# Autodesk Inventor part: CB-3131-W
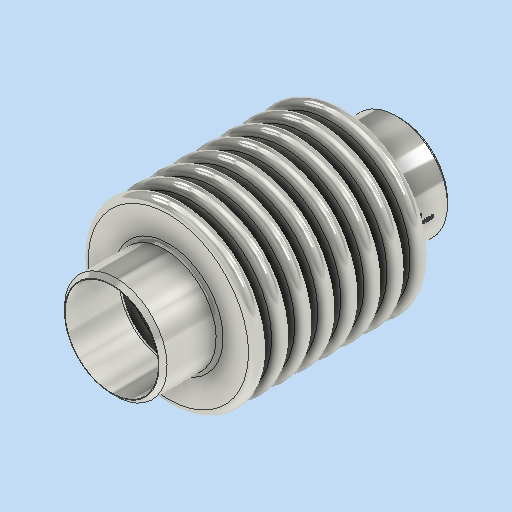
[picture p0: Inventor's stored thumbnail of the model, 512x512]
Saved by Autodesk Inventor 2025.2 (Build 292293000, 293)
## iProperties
Company: DN.RU
Created: 2026-04
Part Number: CB-3131-W
Material: Типовые
Document SubType Name: Modeling
Designer: DN.RU
Density: 6.52243 g/cm^3
Appearance: По умолчанию
Description: D140-02123
Mass: 2100 g
Surface Area: 4937.37 cm^2
Volume: 321.966 cm^3
Author: DN.RU
Title: Компенсатор сильфонный осевой DN.ru Ду80 Ру16
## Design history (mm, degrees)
sketch "Эскиз1"
  geometry: L1 (0, 0)-(0, -125); L2 (44.45, -125)-(44.45, 0); L3 (44.45, 0)-(0, 0); L4 (44.45, 0)-(44.45, -10); L5 (19.45, -10)-(69.45, -10); L6 (19.45, -16)-(69.45, -16); L7 (69.45, -4)-(19.45, -4); L8 (69.45, -15)-(19.45, -15); L9 (19.45, -5)-(69.45, -5); L10 (69.45, -24)-(19.45, -24); L11 (19.45, -25)-(69.45, -25); L12 (19.45, -30)-(69.45, -30); L13 (19.45, -36)-(69.45, -36); L14 (69.45, -35)-(19.45, -35); L15 (69.45, -44)-(19.45, -44); L16 (19.45, -45)-(69.45, -45); L17 (19.45, -50)-(69.45, -50); L18 (19.45, -56)-(69.45, -56); L19 (69.45, -55)-(19.45, -55); L20 (69.45, -64)-(19.45, -64); L21 (19.45, -65)-(69.45, -65); L22 (19.45, -70)-(69.45, -70); L23 (19.45, -76)-(69.45, -76); L24 (69.45, -75)-(19.45, -75); L25 (0, -125)-(44.45, -125); L26 (44.45, -125)-(40.45, -125); L27 (44.45, -64)-(43.45, -64); L28 (40.45, -125)-(40.45, -75); L29 (44.45, -65)-(43.45, -65); L30 (43.45, -65)-(43.45, -55); L31 (44.45, -45)-(43.45, -45); L32 (43.45, -45)-(43.45, -35); L33 (44.45, -25)-(43.45, -25); L34 (43.45, -25)-(43.45, -15); L35 (44.45, -5)-(43.45, -5); L36 (43.45, -5)-(43.45, 0); A1 r 6 centre (19.45, -10) between (19.45, -4) and (19.45, -16); A2 r 6 centre (69.45, -10) between (69.45, -16) and (69.45, -4); A3 r 5 centre (19.45, -10) between (19.45, -5) and (19.45, -15); A4 r 5 centre (69.45, -10) between (69.45, -15) and (69.45, -5); A5 r 5 centre (19.45, -30) between (19.45, -25) and (19.45, -35); A6 r 6 centre (19.45, -30) between (19.45, -24) and (19.45, -36); A7 r 5 centre (69.45, -30) between (69.45, -35) and (69.45, -25); A8 r 6 centre (69.45, -30) between (69.45, -36) and (69.45, -24); A9 r 5 centre (19.45, -50) between (19.45, -45) and (19.45, -55); A10 r 6 centre (19.45, -50) between (19.45, -44) and (19.45, -56); A11 r 5 centre (69.45, -50) between (69.45, -55) and (69.45, -45); A12 r 6 centre (69.45, -50) between (69.45, -56) and (69.45, -44); A13 r 5 centre (19.45, -70) between (19.45, -65) and (19.45, -75); A14 r 6 centre (19.45, -70) between (19.45, -64) and (19.45, -76); A15 r 5 centre (69.45, -70) between (69.45, -75) and (69.45, -65); A16 r 6 centre (69.45, -70) between (69.45, -76) and (69.45, -64); 18 further points
  constraints: 80 end point, 32 point on circle, 16 centre point, 15 point on line, 6 midpoint, 5 perpendicular, 4 tangent, 3 parallel, 2 vertical, 1 horizontal, 69 other
  dimensions: "d0" = 125 distance of L1.start L1.end; "d1" = 44.45 distance of L2.start L1.end; "d3" = 10 distance of L2.end L4.end; "d4" = 25 distance of L4.end L5.end; "d5" = 12 diameter of A2; "d6" = 1 distance between parallel lines of L6 L8; "d9" = 20 distance of L4.end point (44.45, -30); "d14" = 4 distance of L2.start L26.end; "d15" = 1 distance of L27.start L27.end; "d16" = 1 distance of L29.start L29.end; "d17" = 1 distance of L31.start L31.end; "d18" = 1 distance of L33.start L33.end; "d19" = 1 distance of L35.start L35.end
revolve "Вращение1" sketch "Эскиз1" stored, may be unused: angle "d20" = 360 deg
mirror "Зеркальное отражение1"
chamfer "Фаска1" distance "d21" = 3.5; stored, may be unused: second distance "d22" = 2, angle "d23" = 45 deg
fillet "Сопряжение1" dims "d24" = 3
node "РабПлоскость1"
sketch "Эскиз2"
  geometry: L1 (4.893, -83.174)-(4.893, -111.236); L2 (4.893, -111.236)-(-3.237, -111.236); L3 (-3.237, -111.236)-(-3.237, -83.174); L4 (-3.237, -83.174)-(4.893, -83.174); 1 further point
  constraints: 2 other
feature "Рельеф1" sketch "Эскиз2" dims "d25" = 0.1, "d26" = 0
node "Твердое тело1"
node "Эскиз — прямоугольный массив1" dims "d9" = 20, "d12" = 10
